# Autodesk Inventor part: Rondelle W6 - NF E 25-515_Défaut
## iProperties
Shininess: 64.0
Length Units: 11269
Angle Units: 11279
Time Units: 11290
Mass Units: 11283
Length Display Precision: 3
Angle Display Precision: 2
Compacted: True
Part Number: Rondelle W6 - NF E 25-515_Défaut
Document SubType Name: Modeling
Created: 2006-01
Material: Par défaut
Designer: riri
Density: 0.0
Volumn: 0.0
Area: 0.0
PropertySet Name: Model Information
Control State: 0
Master: False
Checked Out: False
Author: riri
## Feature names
1. Base1
